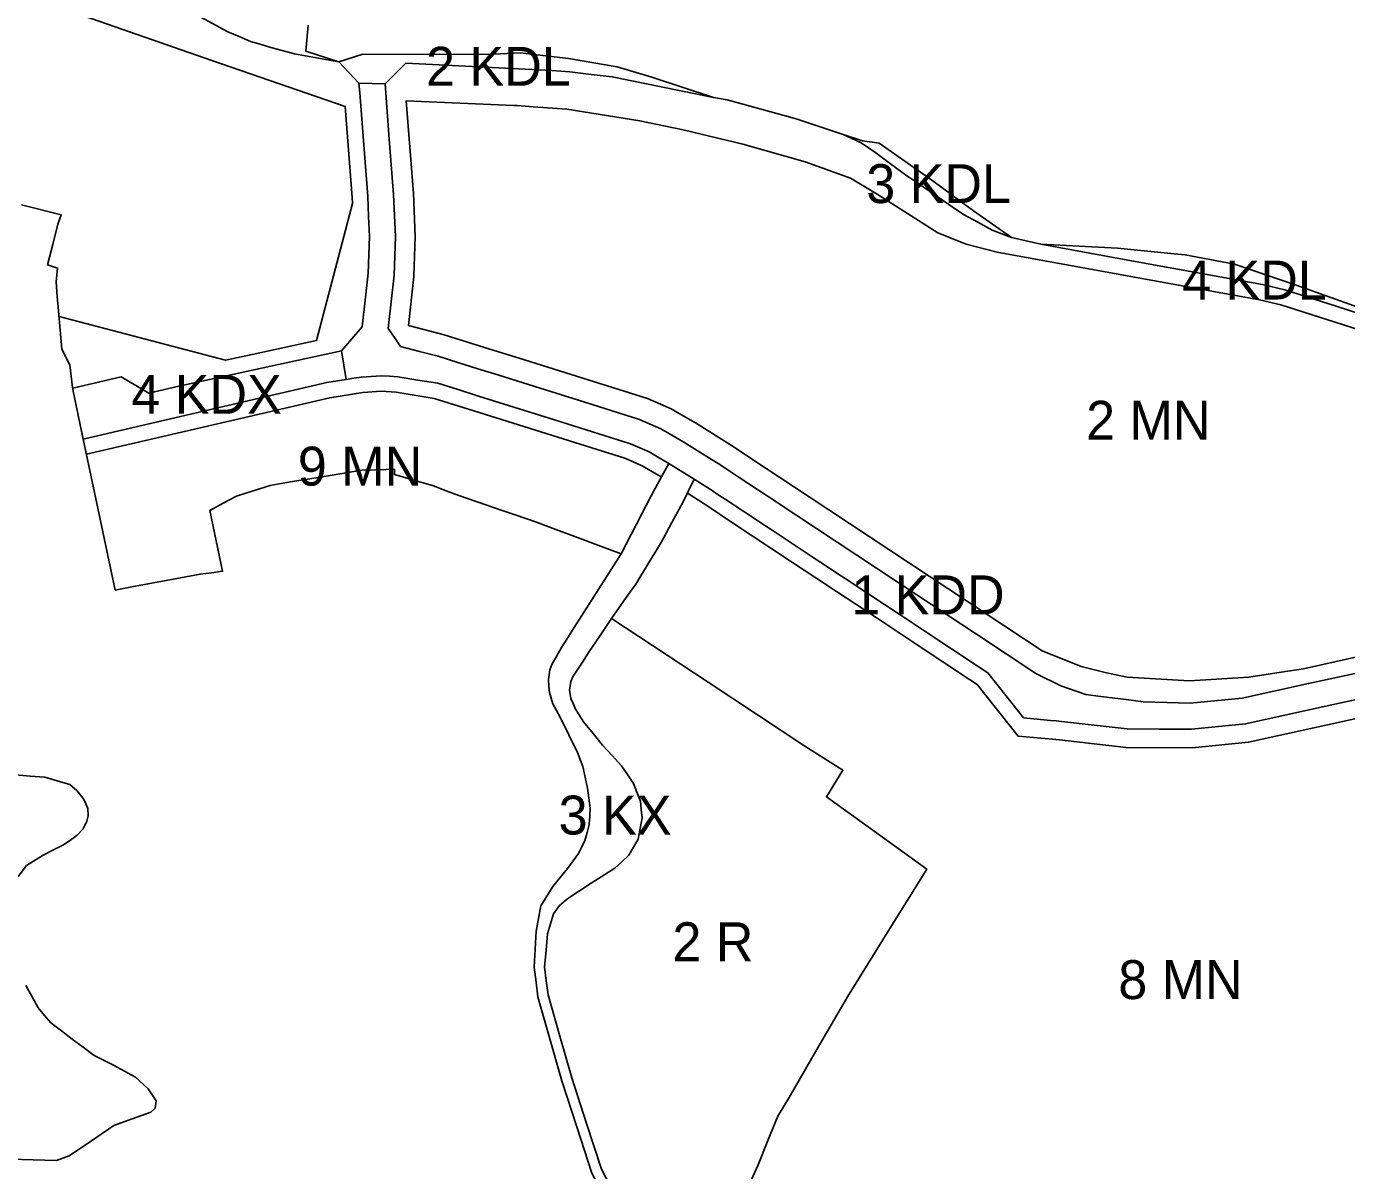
# Model space of a CAD drawing. Extents: x -295551 to -293631, y 22633 to 24461.
# Drawn here: x -294573 to -294065, y 23169 to 23610 of the extents above; entities that cross this region are included whole.
import ezdxf

# ---------------------------------------------------------------- set-up
doc = ezdxf.new("R2010")
doc.units = 0
for name, color, linetype in [('linie_rozgraniczajace', 7, 'Continuous'), ('linie_zabudowy_nieprzekraczalne', 7, 'Continuous'), ('oznaczenia_przeznaczen', 7, 'Continuous')]:
    doc.layers.add(name, color=color, linetype=linetype)

msp = doc.modelspace()

# ---------------------------------------------------------------- linework, layer by layer
at = {"layer": 'linie_rozgraniczajace'}
for points in [[(-294509.179, 23614.935), (-294495.671, 23607.589), (-294491.331, 23605.735), (-294486.991, 23603.881), (-294483.279, 23602.747), (-294479.141, 23601.498), (-294474.795, 23600.331), (-294470.052, 23599.058), (-294461.511, 23597.549), (-294452.97, 23596.04), (-294445.274, 23587.741), (-294444.902, 23584.048), (-294443.349, 23564.052), (-294441.796, 23544.055), (-294441.479, 23536.331), (-294441.162, 23528.607), (-294441.408, 23521.534), (-294441.654, 23514.461), (-294442.813, 23504.154), (-294443.972, 23493.846), (-294451.869, 23484.566), (-294468.474, 23480.942), (-294485.078, 23477.317), (-294499.814, 23474.134), (-294514.549, 23470.951), (-294526.136, 23468.261), (-294536.854, 23474.498), (-294555.51, 23470.167), (-294555.55, 23470.48), (-294556.11, 23474.81), (-294556.67, 23479.14), (-294559.7, 23485.19), (-294560.345, 23492.595), (-294560.99, 23500), (-294561.47, 23505.56), (-294561.95, 23511.12), (-294561.36, 23516.47), (-294565.18, 23517.67), (-294563.22, 23525.535), (-294561.26, 23533.4), (-294559.94, 23537.03), (-294575.31, 23540.915)], [(-294464.78, 23610.16), (-294465.709, 23600.064), (-294452.97, 23596.04), (-294461.511, 23597.549), (-294470.052, 23599.058), (-294474.795, 23600.331), (-294479.141, 23601.498), (-294483.279, 23602.747), (-294486.991, 23603.881), (-294491.331, 23605.735), (-294495.671, 23607.589), (-294509.179, 23614.935)], [(-294435.144, 23587.552), (-294427.065, 23595.429), (-294398.979, 23594.036), (-294370.893, 23592.643), (-294363.88, 23592.079), (-294355.716, 23591.154), (-294347.552, 23590.228), (-294328.051, 23586.264), (-294308.55, 23582.3), (-294303.2, 23581.3), (-294276.68, 23573.97), (-294258.53, 23567.972), (-294251.857, 23564.924), (-294251.591, 23564.802), (-294246.006, 23560.888), (-294240.292, 23556.67), (-294234.577, 23552.453), (-294227.681, 23547.747), (-294220.784, 23543.04), (-294216.489, 23540.109), (-294212.193, 23537.177), (-294206.667, 23534.133), (-294201.141, 23531.089), (-294193.68, 23528.3), (-294182.34, 23525.63), (-294144.625, 23518.811), (-294106.88, 23511.986), (-294096.884, 23510.136), (-294088.253, 23508.089), (-294068.504, 23501.732), (-294048.754, 23495.375)], [(-294451.869, 23484.566), (-294443.972, 23493.846), (-294442.813, 23504.154), (-294441.654, 23514.461), (-294441.408, 23521.534), (-294441.162, 23528.607), (-294441.479, 23536.331), (-294441.796, 23544.055), (-294443.349, 23564.052), (-294444.902, 23584.048), (-294445.274, 23587.741), (-294435.144, 23587.552), (-294434.174, 23575.09), (-294433.481, 23566.178), (-294431.818, 23544.803), (-294431.487, 23536.721), (-294431.155, 23528.639), (-294431.414, 23521.183), (-294431.674, 23513.728), (-294432.83, 23503.44), (-294433.987, 23493.152), (-294431.548, 23489.69), (-294429.109, 23486.229), (-294421.9, 23484.364), (-294414.69, 23482.498), (-294407.013, 23480.091), (-294399.335, 23477.685), (-294391.67, 23475.282), (-294384.005, 23472.879), (-294360.499, 23465.511), (-294336.994, 23458.143), (-294332.881, 23456.324), (-294328.768, 23454.505), (-294324.617, 23452.09), (-294319.945, 23449.373), (-294312.809, 23444.906), (-294305.672, 23440.44), (-294302.126, 23438.095), (-294298.579, 23435.751), (-294287.492, 23428.42), (-294276.405, 23421.09), (-294253.262, 23405.788), (-294230.119, 23390.487), (-294207.203, 23375.335), (-294184.287, 23360.184), (-294174.689, 23355.463), (-294164.999, 23352.036), (-294159.266, 23351.298), (-294149.416, 23350.087), (-294142.874, 23349.283), (-294133.808, 23349.022), (-294124.743, 23348.761), (-294104.81, 23350.689), (-294079.145, 23356.259), (-294053.48, 23361.83)], [(-294207.203, 23375.335), (-294230.119, 23390.487), (-294253.262, 23405.788), (-294276.405, 23421.09), (-294287.492, 23428.42), (-294298.579, 23435.751), (-294302.126, 23438.095), (-294305.672, 23440.44), (-294312.809, 23444.906), (-294319.945, 23449.373), (-294324.617, 23452.09), (-294328.768, 23454.505), (-294332.881, 23456.324), (-294336.994, 23458.143), (-294360.499, 23465.511), (-294384.005, 23472.879), (-294391.67, 23475.282), (-294399.335, 23477.685), (-294407.013, 23480.091), (-294414.69, 23482.498), (-294421.9, 23484.364), (-294429.109, 23486.229), (-294431.548, 23489.69), (-294433.987, 23493.152), (-294432.83, 23503.44), (-294431.674, 23513.728), (-294431.414, 23521.183), (-294431.155, 23528.639), (-294431.487, 23536.721), (-294431.818, 23544.803), (-294433.481, 23566.178), (-294434.174, 23575.09), (-294435.144, 23587.552)], [(-294575.31, 23540.915), (-294559.94, 23537.03), (-294561.26, 23533.4), (-294563.22, 23525.535), (-294565.18, 23517.67), (-294561.36, 23516.47), (-294561.95, 23511.12), (-294561.47, 23505.56), (-294560.99, 23500), (-294560.345, 23492.595), (-294559.7, 23485.19), (-294556.67, 23479.14), (-294556.11, 23474.81), (-294555.55, 23470.48), (-294555.51, 23470.167), (-294555.369, 23469.079), (-294553.409, 23459.825), (-294551.45, 23450.57), (-294545.282, 23421.437), (-294539.114, 23392.305), (-294532.67, 23393.62), (-294519.545, 23396.045), (-294506.42, 23398.47), (-294502.085, 23399.03), (-294497.75, 23399.59), (-294500.18, 23411.33), (-294502.61, 23423.07), (-294497.47, 23425.785), (-294492.33, 23428.5), (-294485.9, 23430.55), (-294479.47, 23432.6), (-294475.145, 23433.39), (-294470.82, 23434.18), (-294466.625, 23434.86), (-294462.43, 23435.54), (-294453.98, 23436.91), (-294444.103, 23438.511), (-294437.917, 23438.72), (-294431.44, 23438.94), (-294431.53, 23436.88), (-294424, 23434.685), (-294416.47, 23432.49)], [(-294242.56, 23386.724), (-294250.187, 23391.767), (-294257.814, 23396.81), (-294260.605, 23398.655), (-294265.329, 23401.779), (-294270.053, 23404.902), (-294274.778, 23408.026), (-294278.928, 23410.769), (-294286.672, 23415.89), (-294290.267, 23418.267), (-294294.648, 23421.163), (-294299.029, 23424.06), (-294303.047, 23426.716), (-294307.064, 23429.373), (-294309.074, 23430.701), (-294311.083, 23432.03), (-294315.937, 23435.067), (-294325.734, 23441.171), (-294329.526, 23443.377), (-294333.319, 23445.584), (-294340.523, 23448.77), (-294369.835, 23457.958), (-294399.148, 23467.146), (-294406.988, 23469.604), (-294414.828, 23472.061), (-294422.514, 23473.316), (-294430.2, 23474.57), (-294433.415, 23474.772), (-294436.63, 23474.974), (-294440.489, 23474.725), (-294444.349, 23474.476), (-294447.213, 23474.021), (-294450.078, 23473.567), (-294451.869, 23484.566)], [(-294377.63, 23246.92), (-294377.27, 23253.892), (-294376.909, 23260.865), (-294375.973, 23265.701), (-294375.037, 23270.538), (-294370.444, 23278.103), (-294367.612, 23281.551), (-294364.779, 23284.998), (-294362.662, 23287.909), (-294360.545, 23290.82), (-294359.33, 23293.292), (-294358.115, 23295.764), (-294357.267, 23298.886), (-294356.419, 23302.009), (-294356.254, 23305.148), (-294356.09, 23308.287), (-294356.56, 23312.152), (-294357.031, 23316.016), (-294357.989, 23320.143), (-294358.947, 23324.27), (-294359.958, 23327.006), (-294360.97, 23329.742), (-294364.284, 23336.548), (-294367.599, 23343.353), (-294369.058, 23345.94), (-294370.517, 23348.526), (-294371.151, 23350.668), (-294371.784, 23352.809), (-294371.965, 23355.313), (-294372.146, 23357.816), (-294371.875, 23359.716), (-294371.604, 23361.617), (-294370.82, 23363.68), (-294368.945, 23366.955), (-294367.07, 23370.23), (-294365.115, 23373.355), (-294363.16, 23376.48), (-294353.67, 23391.385), (-294344.18, 23406.29), (-294338.385, 23417.5), (-294332.59, 23428.71), (-294329.22, 23434.835), (-294325.734, 23441.171), (-294315.937, 23435.067), (-294320.36, 23426.04), (-294324.525, 23418.39), (-294328.69, 23410.74), (-294333.59, 23402.645), (-294338.49, 23394.55), (-294341.229, 23390.699), (-294347.821, 23381.432), (-294352.239, 23374.818), (-294356.657, 23368.204), (-294358.746, 23364.903), (-294362.556, 23359.131), (-294363.562, 23357.148), (-294363.976, 23353.791), (-294363.533, 23350.553), (-294362.681, 23348.64), (-294361.829, 23346.727), (-294358.58, 23341.487), (-294354.956, 23337.015), (-294351.332, 23332.543), (-294347.646, 23328.589), (-294343.961, 23324.636), (-294341.678, 23321.209), (-294339.396, 23317.782), (-294338.034, 23314.38), (-294336.672, 23310.978), (-294336.348, 23307.764), (-294336.024, 23304.55), (-294337.597, 23296.363), (-294341.172, 23290.101), (-294343.882, 23287.617), (-294346.592, 23285.133), (-294355.663, 23279.287), (-294364.734, 23273.442), (-294367.825, 23270.704), (-294370.173, 23267.508), (-294371.355, 23263.638), (-294372.537, 23259.768), (-294373.077, 23253.413), (-294373.618, 23247.059), (-294372.967, 23241.697), (-294372.317, 23236.335), (-294367.745, 23220.326), (-294363.173, 23204.317), (-294357.45, 23186.698), (-294351.727, 23169.079), (-294348.142, 23162.198)], [(-294347.821, 23381.432), (-294341.229, 23390.699), (-294338.49, 23394.55), (-294333.59, 23402.645), (-294328.69, 23410.74), (-294324.525, 23418.39), (-294320.36, 23426.04), (-294315.937, 23435.067), (-294311.083, 23432.03), (-294309.074, 23430.701), (-294307.064, 23429.373), (-294303.047, 23426.716), (-294299.029, 23424.06), (-294294.648, 23421.163), (-294290.267, 23418.267), (-294286.672, 23415.89), (-294278.928, 23410.769), (-294274.778, 23408.026), (-294270.053, 23404.902), (-294265.329, 23401.779), (-294260.605, 23398.655), (-294257.814, 23396.81), (-294250.187, 23391.767), (-294242.56, 23386.724), (-294238.088, 23383.767), (-294233.616, 23380.811), (-294226.693, 23376.233), (-294216.803, 23369.694), (-294206.914, 23363.156), (-294202.768, 23360.414), (-294195.894, 23351.727), (-294189.02, 23343.04), (-294183.8, 23342.555), (-294178.58, 23342.07), (-294176.505, 23341.88), (-294174.43, 23341.69), (-294161.765, 23340.275), (-294149.1, 23338.86), (-294136.706, 23338.775), (-294124.312, 23338.69), (-294113.871, 23339.729), (-294103.43, 23340.769), (-294073.191, 23347.416), (-294042.952, 23354.064)], [(-294416.47, 23432.49), (-294411.6, 23430.635), (-294406.73, 23428.78), (-294400, 23426.464), (-294395.86, 23425.04), (-294390.43, 23423.175), (-294385, 23421.31), (-294380.87, 23419.89), (-294376.74, 23418.47), (-294369.36, 23415.71), (-294361.98, 23412.95), (-294353.08, 23409.62), (-294344.18, 23406.29), (-294353.67, 23391.385), (-294363.16, 23376.48), (-294365.115, 23373.355), (-294367.07, 23370.23), (-294368.945, 23366.955), (-294370.82, 23363.68), (-294371.604, 23361.617), (-294371.875, 23359.716), (-294372.146, 23357.816), (-294371.965, 23355.313), (-294371.784, 23352.809), (-294371.151, 23350.668), (-294370.517, 23348.526), (-294369.058, 23345.94), (-294367.599, 23343.353), (-294364.284, 23336.548), (-294360.97, 23329.742), (-294359.958, 23327.006), (-294358.947, 23324.27), (-294357.989, 23320.143), (-294357.031, 23316.016), (-294356.56, 23312.152), (-294356.09, 23308.287), (-294356.254, 23305.148), (-294356.419, 23302.009), (-294357.267, 23298.886), (-294358.115, 23295.764), (-294359.33, 23293.292), (-294360.545, 23290.82), (-294362.662, 23287.909), (-294364.779, 23284.998), (-294367.612, 23281.551), (-294370.444, 23278.103), (-294375.037, 23270.538), (-294375.973, 23265.701), (-294376.909, 23260.865), (-294377.27, 23253.892), (-294377.63, 23246.92), (-294376.94, 23241.23), (-294376.25, 23235.54), (-294371.625, 23219.345), (-294367, 23203.15), (-294361.214, 23185.338), (-294355.428, 23167.526)], [(-294042.952, 23354.064), (-294073.191, 23347.416), (-294103.43, 23340.769), (-294113.871, 23339.729), (-294124.312, 23338.69), (-294136.706, 23338.775), (-294149.1, 23338.86), (-294161.765, 23340.275), (-294174.43, 23341.69), (-294176.505, 23341.88), (-294178.58, 23342.07), (-294183.8, 23342.555), (-294189.02, 23343.04), (-294195.894, 23351.727), (-294202.768, 23360.414), (-294206.914, 23363.156), (-294216.803, 23369.694), (-294226.693, 23376.233), (-294233.616, 23380.811), (-294238.088, 23383.767), (-294242.56, 23386.724)], [(-294348.142, 23162.198), (-294351.727, 23169.079), (-294357.45, 23186.698), (-294363.173, 23204.317), (-294367.745, 23220.326), (-294372.317, 23236.335), (-294372.967, 23241.697), (-294373.618, 23247.059), (-294373.077, 23253.413), (-294372.537, 23259.768), (-294371.355, 23263.638), (-294370.173, 23267.508), (-294367.825, 23270.704), (-294364.734, 23273.442), (-294355.663, 23279.287), (-294346.592, 23285.133), (-294343.882, 23287.617), (-294341.172, 23290.101), (-294337.597, 23296.363), (-294336.024, 23304.55), (-294336.348, 23307.764), (-294336.672, 23310.978), (-294338.034, 23314.38), (-294339.396, 23317.782), (-294341.678, 23321.209), (-294343.961, 23324.636), (-294347.646, 23328.589), (-294351.332, 23332.543), (-294354.956, 23337.015), (-294358.58, 23341.487), (-294361.829, 23346.727), (-294362.681, 23348.64), (-294363.533, 23350.553), (-294363.976, 23353.791), (-294363.562, 23357.148), (-294362.556, 23359.131), (-294358.746, 23364.903), (-294356.657, 23368.204), (-294352.239, 23374.818), (-294347.821, 23381.432), (-294310.593, 23356.771), (-294273.366, 23332.11), (-294266.05, 23327.498), (-294258.735, 23322.885), (-294265.024, 23312.665), (-294245.664, 23298.719), (-294226.304, 23284.773), (-294241.602, 23260.147), (-294256.9, 23235.52), (-294268.155, 23216.13), (-294279.41, 23196.74), (-294283.76, 23189.54), (-294287.525, 23180.15), (-294291.29, 23170.76), (-294295.355, 23162.035)], [(-294295.355, 23162.035), (-294291.29, 23170.76), (-294287.525, 23180.15), (-294283.76, 23189.54), (-294279.41, 23196.74), (-294268.155, 23216.13), (-294256.9, 23235.52), (-294241.602, 23260.147), (-294226.304, 23284.773), (-294245.664, 23298.719), (-294265.024, 23312.665), (-294258.735, 23322.885), (-294266.05, 23327.498), (-294273.366, 23332.11), (-294310.593, 23356.771), (-294347.821, 23381.432)], [(-294053.48, 23361.83), (-294079.145, 23356.259), (-294104.81, 23350.689), (-294124.743, 23348.761), (-294133.808, 23349.022), (-294142.874, 23349.283), (-294149.416, 23350.087), (-294159.266, 23351.298), (-294164.999, 23352.036), (-294174.689, 23355.463), (-294184.287, 23360.184), (-294207.203, 23375.335)], [(-294576.599, 23281.855), (-294573.352, 23286.095), (-294566.909, 23290.178), (-294563.143, 23292.081), (-294559.376, 23293.984), (-294556.381, 23295.964), (-294553.755, 23297.898), (-294551.498, 23300.318), (-294550.021, 23303.27), (-294549.618, 23305.281), (-294549.708, 23308.143), (-294550.839, 23310.807), (-294551.47, 23311.97), (-294553.85, 23314.957), (-294556.673, 23317.39), (-294561.478, 23318.774), (-294566.283, 23320.157), (-294571.918, 23320.648), (-294577.553, 23321.14)], [(-294577.553, 23321.14), (-294571.918, 23320.648), (-294566.283, 23320.157), (-294561.478, 23318.774), (-294556.673, 23317.39), (-294553.85, 23314.957), (-294551.47, 23311.97), (-294550.839, 23310.807), (-294549.708, 23308.143), (-294549.618, 23305.281), (-294550.021, 23303.27), (-294551.498, 23300.318), (-294553.755, 23297.898), (-294556.381, 23295.964), (-294559.376, 23293.984), (-294563.143, 23292.081), (-294566.909, 23290.178), (-294573.352, 23286.095), (-294576.599, 23281.855)], [(-294334.587, 23131.929), (-294339.381, 23136.853), (-294342.73, 23142.148), (-294345.337, 23147.655), (-294347.944, 23153.161), (-294351.686, 23160.344), (-294355.428, 23167.526), (-294361.214, 23185.338), (-294367, 23203.15), (-294371.625, 23219.345), (-294376.25, 23235.54), (-294376.94, 23241.23), (-294377.63, 23246.92)], [(-294579.66, 23172.908), (-294570.733, 23172.653), (-294561.806, 23172.398), (-294556.82, 23174.18), (-294548.27, 23180.055), (-294539.72, 23185.93), (-294532.575, 23188.51), (-294525.43, 23191.09), (-294523.778, 23192.612), (-294523.408, 23195.385), (-294526.413, 23200.006), (-294531.294, 23204.544), (-294535.517, 23206.875), (-294539.74, 23209.206), (-294547.221, 23212.904), (-294551.484, 23216.079), (-294555.747, 23219.254), (-294559.871, 23222.381), (-294563.995, 23225.508), (-294566.401, 23228.371), (-294568.806, 23231.235), (-294571.176, 23235.548), (-294573.547, 23239.861)], [(-294573.547, 23239.861), (-294571.176, 23235.548), (-294568.806, 23231.235), (-294566.401, 23228.371), (-294563.995, 23225.508), (-294559.871, 23222.381), (-294555.747, 23219.254), (-294551.484, 23216.079), (-294547.221, 23212.904), (-294539.74, 23209.206), (-294535.517, 23206.875), (-294531.294, 23204.544), (-294526.413, 23200.006), (-294523.408, 23195.385), (-294523.778, 23192.612), (-294525.43, 23191.09), (-294532.575, 23188.51), (-294539.72, 23185.93), (-294548.27, 23180.055), (-294556.82, 23174.18), (-294561.806, 23172.398), (-294570.733, 23172.653), (-294579.66, 23172.908)]]:
    msp.add_lwpolyline(points, dxfattribs=at)
for points in [[(-294452.97, 23596.04), (-294443.64, 23598.99), (-294395.7, 23598.78), (-294383.04, 23599.46), (-294364.43, 23597.33), (-294345.68, 23594.04), (-294332.3, 23590.05), (-294308.55, 23582.3), (-294328.051, 23586.264), (-294347.552, 23590.228), (-294355.716, 23591.154), (-294363.88, 23592.079), (-294370.893, 23592.643), (-294398.979, 23594.036), (-294427.065, 23595.429), (-294435.144, 23587.552), (-294445.274, 23587.741)], [(-294258.53, 23567.972), (-294251.05, 23565.5), (-294244.64, 23564.64), (-294225.27, 23550.99), (-294221.6, 23548.29), (-294213.55, 23542.37), (-294208.29, 23538.51), (-294193.68, 23528.3), (-294201.141, 23531.089), (-294206.667, 23534.133), (-294212.193, 23537.177), (-294216.489, 23540.109), (-294220.784, 23543.04), (-294227.681, 23547.747), (-294234.577, 23552.453), (-294240.292, 23556.67), (-294246.006, 23560.888), (-294251.591, 23564.802), (-294251.857, 23564.924)], [(-294182.34, 23525.63), (-294152.87, 23524.09), (-294130.97, 23521.97), (-294126.79, 23521.57), (-294107.65, 23517.99), (-294083.96, 23509.85), (-294048.2, 23497.14), (-294018.48, 23487.36), (-294012.99, 23485.57), (-293997.701, 23481.109), (-294005.943, 23482.872), (-294014.185, 23484.635), (-294027.81, 23488.827), (-294041.436, 23493.02), (-294048.754, 23495.375), (-294068.504, 23501.732), (-294088.253, 23508.089), (-294096.884, 23510.136), (-294106.88, 23511.986), (-294144.625, 23518.811)], [(-294555.51, 23470.167), (-294536.854, 23474.498), (-294526.136, 23468.261), (-294514.549, 23470.951), (-294499.814, 23474.134), (-294485.078, 23477.317), (-294468.474, 23480.942), (-294451.869, 23484.566), (-294450.078, 23473.567), (-294457.608, 23472.372), (-294504.529, 23461.471), (-294551.45, 23450.57), (-294553.409, 23459.825), (-294555.369, 23469.079)], [(-294551.45, 23450.57), (-294504.529, 23461.471), (-294457.608, 23472.372), (-294450.078, 23473.567), (-294447.213, 23474.021), (-294444.349, 23474.476), (-294440.489, 23474.725), (-294436.63, 23474.974), (-294433.415, 23474.772), (-294430.2, 23474.57), (-294422.514, 23473.316), (-294414.828, 23472.061), (-294406.988, 23469.604), (-294399.148, 23467.146), (-294369.835, 23457.958), (-294340.523, 23448.77), (-294333.319, 23445.584), (-294329.526, 23443.377), (-294325.734, 23441.171), (-294329.22, 23434.835), (-294332.59, 23428.71), (-294338.385, 23417.5), (-294344.18, 23406.29), (-294353.08, 23409.62), (-294361.98, 23412.95), (-294369.36, 23415.71), (-294376.74, 23418.47), (-294380.87, 23419.89), (-294385, 23421.31), (-294390.43, 23423.175), (-294395.86, 23425.04), (-294400, 23426.464), (-294406.73, 23428.78), (-294411.6, 23430.635), (-294416.47, 23432.49), (-294424, 23434.685), (-294431.53, 23436.88), (-294431.44, 23438.94), (-294437.917, 23438.72), (-294444.103, 23438.511), (-294453.98, 23436.91), (-294462.43, 23435.54), (-294466.625, 23434.86), (-294470.82, 23434.18), (-294475.145, 23433.39), (-294479.47, 23432.6), (-294485.9, 23430.55), (-294492.33, 23428.5), (-294497.47, 23425.785), (-294502.61, 23423.07), (-294500.18, 23411.33), (-294497.75, 23399.59), (-294502.085, 23399.03), (-294506.42, 23398.47), (-294519.545, 23396.045), (-294532.67, 23393.62), (-294539.114, 23392.305), (-294545.282, 23421.437)]]:
    msp.add_lwpolyline(points, close=True, dxfattribs=at)
at = {"layer": 'linie_zabudowy_nieprzekraczalne'}
for points in [[(-294560.797, 23497.781), (-294496.638, 23480.953), (-294486.351, 23483.18), (-294461.593, 23488.508), (-294447.691, 23541.378), (-294447.787, 23543.699), (-294450.499, 23578.776), (-294501.86, 23596.55), (-294568.38, 23619.57)], [(-294426.933, 23580.953), (-294424.156, 23545.259), (-294423.475, 23528.663), (-294424.014, 23513.165), (-294426.128, 23494.365), (-294412.319, 23490.792), (-294396.756, 23485.913), (-294381.426, 23481.108), (-294333.95, 23466.226), (-294324.844, 23462.199), (-294320.281, 23459.544), (-294315.489, 23456.756), (-294301.006, 23447.693), (-294293.823, 23442.944), (-294271.65, 23428.283), (-294225.363, 23397.68), (-294181.896, 23368.94), (-294166.787, 23362.891), (-294156.987, 23360.412), (-294156.987, 23360.412), (-294149.066, 23358.796), (-294149.066, 23358.796), (-294125.035, 23357.396), (-294102.222, 23358.819), (-294089.718, 23360.746), (-294081.141, 23361.966), (-294026.79, 23374.14)], [(-294034.397, 23484.576), (-294084.231, 23500.491), (-294089.867, 23502.306), (-294098.123, 23504.263), (-294107.96, 23506.084), (-294146.194, 23512.998), (-294199.207, 23522.599), (-294211.159, 23525.753), (-294222.035, 23530.087), (-294245.391, 23544.924), (-294245.391, 23544.924), (-294255.77, 23551.1), (-294273.21, 23557.474), (-294273.21, 23557.474), (-294297.178, 23564.264), (-294297.178, 23564.264), (-294320.268, 23569.81), (-294320.268, 23569.81), (-294336.865, 23573.184), (-294336.865, 23573.184), (-294336.865, 23573.184), (-294365.075, 23577.743), (-294365.075, 23577.743), (-294377.991, 23578.686), (-294384.165, 23579.159), (-294385.531, 23579.203), (-294426.933, 23580.953)], [(-294328.627, 23435.913), (-294328.751, 23435.985), (-294336.049, 23440.23), (-294342.64, 23443.146), (-294400.942, 23461.421), (-294416.215, 23466.208), (-294430.873, 23468.6), (-294436.625, 23468.962), (-294443.684, 23468.506), (-294456.457, 23466.48), (-294550.207, 23444.699)], [(-294041.391, 23347.069), (-294102.302, 23333.679), (-294123.981, 23331.52), (-294149.524, 23331.696), (-294175.155, 23334.559), (-294179.238, 23334.933), (-294191.131, 23336.038), (-294206.877, 23355.939), (-294210.223, 23358.151), (-294230.002, 23371.228), (-294236.925, 23375.806), (-294245.869, 23381.719), (-294261.123, 23391.805), (-294268.638, 23396.774), (-294278.087, 23403.021), (-294286.387, 23408.508), (-294293.576, 23413.262), (-294302.338, 23419.055), (-294310.373, 23424.368), (-294314.33, 23426.983), (-294318.591, 23429.65)]]:
    msp.add_lwpolyline(points, dxfattribs=at)

# ---------------------------------------------------------------- texts
at = {"layer": 'oznaczenia_przeznaczen'}
for s, p in [('2 KDL', (-294419.308, 23586.765)), ('3 KDL', (-294249.628, 23541.534)), ('4 KDL', (-294127.897, 23504.357)), ('4 KDX', (-294532.899, 23460.299)), ('2 MN', (-294164.899, 23450.307)), ('9 MN', (-294468.746, 23432.614)), ('1 KDD', (-294255.418, 23382.987)), ('3 KX', (-294368.21, 23298.1)), ('2 R', (-294324.351, 23249.242)), ('8 MN', (-294152.487, 23234.656))]:
    msp.add_text(s, height=15, dxfattribs=at).set_placement(p)

doc.saveas('drawing.dxf')
